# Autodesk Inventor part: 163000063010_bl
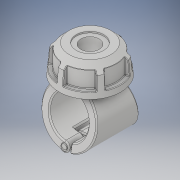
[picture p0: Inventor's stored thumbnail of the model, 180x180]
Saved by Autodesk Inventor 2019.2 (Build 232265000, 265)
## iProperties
Created: 2022-02
Part Number: 163000063010_bl
Material: Generic
Description: Plassadle Threaded 63x1''
Document SubType Name: Modeling
Designer: comp2
Density: 1 g/cm^3
Appearance: Default
Author: comp2
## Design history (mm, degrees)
derived "16300.ipt"
feature "Solid1::16300.ipt" dims "ScaleForDerivedMember" = 10
feature "Solid2::16300.ipt" dims "ScaleForDerivedMember" = 10
feature "Solid3::16300.ipt" dims "ScaleForDerivedMember" = 10
feature "Solid4::16300.ipt" dims "ScaleForDerivedMember" = 10
tag "TaggingFeature1"
body "Solid1"
body "Solid2"
body "Solid3"
body "Solid4"
other parameters: "d0" = 63 [user parameter], "d2" = 91 [user parameter], "d3" = 31.5 [user parameter], "d7" = 86.45 [user parameter], "d8" = 85 deg [user parameter], "d9" = 45 deg [user parameter], "d10" = 102 [user parameter], "d11" = 49 [user parameter], "d12" = 31.8185 [user parameter], "d13" = 42.84 [user parameter], "d14" = 45.4365 [user parameter], "d42" = 2.8 [user parameter], "d49" = 1.82 [user parameter], "d50" = 89 [user parameter], "d51" = 0 [user parameter], "d52" = 19.6 [user parameter], "d53" = 50.05 [user parameter], "d54" = 31.15 [user parameter], "d55" = 0 [user parameter], "d56" = 17.8 [user parameter], "d57" = 17.8 [user parameter], "d59" = 0 [user parameter], "d60" = 89 [user parameter], "d61" = 0 [user parameter], "d62" = 31.15 [user parameter], "d63" = 0 [user parameter], "d65" = 0 [user parameter], "d67" = 0 [user parameter], "d69" = 0 [user parameter], "d70" = 1 [user parameter], "d71" = 85.44 [user parameter], "d72" = 0 [user parameter], "d73" = 2 [user parameter], "d78" = 86.7 [user parameter], "d79" = 5.1 [user parameter], "d80" = 60 deg [user parameter], "d81" = 5.1 [user parameter], "d84" = 0 [user parameter], "d85" = 1 [user parameter], "d87" = 360 deg [user parameter], "d122" = 49 [user parameter], "d124" = 42.80128 [user parameter], "d125" = 2.27275 [user parameter], "d127" = 136 [user parameter], "d129" = 30.291 [user parameter], "d130" = 25.74735 [user parameter], "d131" = 31.85 [user parameter], "d132" = 45 deg [user parameter], "d133" = 22.295 [user parameter], "d134" = 15.1455 [user parameter], "d136" = 0 [user parameter], "d138" = 0 [user parameter], "d" = 63 [user parameter], "d1" = 25 [user parameter], "B" = 91 [user parameter], "L" = 89 [user parameter], "E_" = 54 [user parameter], "E1" = 102 [user parameter], "H1" = 136 [user parameter], "H2" = 49 [user parameter], "H3" = 78 [user parameter], "H_costum" = 49 [user parameter], "Rp" = 30.291 [user parameter], "d128" = 45.455 [user parameter]
